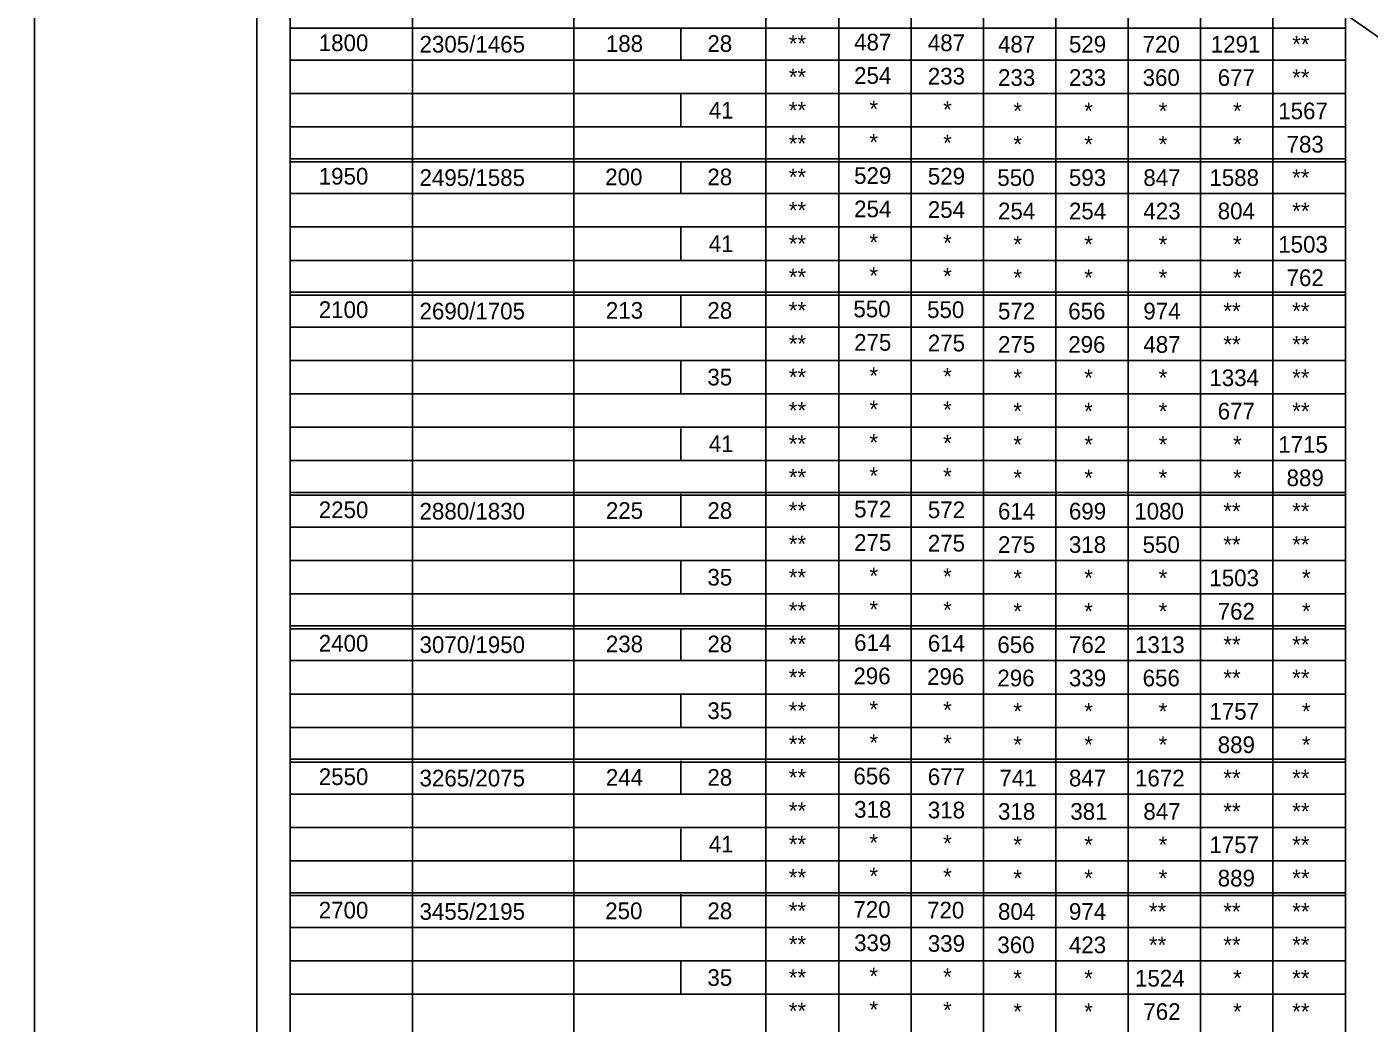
# Model space of a CAD drawing. Extents: x -22562 to -18409, y 3991 to 7171.
# Drawn here: x -21227.2 to -20985.9, y 4239.8 to 4419 of the extents above; entities that cross this region are included whole.
import ezdxf

# ---------------------------------------------------------------- set-up
doc = ezdxf.new("R2010")
doc.units = 0
for name, color, linetype in [('2', 7, 'Continuous'), ('Default', 7, 'Continuous'), ('PLT-BNDY', 7, 'Continuous')]:
    doc.layers.add(name, color=color, linetype=linetype)

msp = doc.modelspace()

# ---------------------------------------------------------------- linework, layer by layer
at = {"layer": '2'}
for p, q in [((-21185.85, 4006.37), (-21185.85, 4570.37)), ((-21179.85, 4553.87), (-21179.85, 4190.99)), ((-20990.1, 4553.87), (-20990.1, 4190.99)), ((-21094.35, 4546.12), (-21094.35, 4190.99)), ((-21157.85, 4540.37), (-21157.85, 4190.99)), ((-21128.85, 4540.37), (-21128.85, 4190.99)), ((-21081.22, 4540.37), (-21081.22, 4190.99)), ((-21068.22, 4540.37), (-21068.22, 4190.99)), ((-21055.22, 4540.37), (-21055.22, 4190.99)), ((-21042.22, 4540.37), (-21042.22, 4190.99)), ((-21029.22, 4540.37), (-21029.22, 4190.99)), ((-21016.22, 4540.37), (-21016.22, 4190.99)), ((-21003.22, 4540.37), (-21003.22, 4190.99)), ((-21179.85, 4418.74), (-20990.1, 4418.74)), ((-21109.6, 4418.74), (-21109.6, 4412.99)), ((-21179.85, 4412.99), (-20990.1, 4412.99)), ((-21179.85, 4406.99), (-20990.1, 4406.99)), ((-21109.6, 4406.99), (-21109.6, 4400.99)), ((-21179.85, 4400.99), (-20990.1, 4400.99)), ((-21179.85, 4395.24), (-20990.1, 4395.24)), ((-21179.85, 4394.74), (-20990.1, 4394.74)), ((-21109.6, 4394.74), (-21109.6, 4388.99)), ((-21179.85, 4388.99), (-20990.1, 4388.99)), ((-21179.85, 4382.99), (-20990.1, 4382.99)), ((-21109.6, 4382.99), (-21109.6, 4376.99)), ((-21179.85, 4376.99), (-20990.1, 4376.99)), ((-21179.85, 4371.24), (-20990.1, 4371.24)), ((-21179.85, 4370.74), (-20990.1, 4370.74)), ((-21109.6, 4370.74), (-21109.6, 4364.99)), ((-21179.85, 4364.99), (-20990.1, 4364.99)), ((-21179.85, 4358.99), (-20990.1, 4358.99)), ((-21109.6, 4358.99), (-21109.6, 4352.99)), ((-21179.85, 4352.99), (-20990.1, 4352.99)), ((-21179.85, 4346.99), (-20990.1, 4346.99)), ((-21109.6, 4346.74), (-21109.6, 4340.99)), ((-21179.85, 4340.99), (-20990.1, 4340.99)), ((-21179.85, 4335.24), (-20990.1, 4335.24)), ((-21179.85, 4334.74), (-20990.1, 4334.74)), ((-21109.6, 4334.99), (-21109.6, 4328.99)), ((-21179.85, 4328.99), (-20990.1, 4328.99)), ((-21179.85, 4322.99), (-20990.1, 4322.99)), ((-21109.6, 4322.99), (-21109.6, 4316.99)), ((-21179.85, 4316.99), (-20990.1, 4316.99)), ((-21179.85, 4311.24), (-20990.1, 4311.24)), ((-21179.85, 4310.74), (-20990.1, 4310.74)), ((-21109.6, 4310.74), (-21109.6, 4304.99)), ((-21179.85, 4304.99), (-20990.1, 4304.99)), ((-21179.85, 4298.99), (-20990.1, 4298.99)), ((-21109.6, 4298.99), (-21109.6, 4292.99)), ((-21179.85, 4292.99), (-20990.1, 4292.99)), ((-21179.85, 4287.24), (-20990.1, 4287.24)), ((-21179.85, 4286.74), (-20990.1, 4286.74)), ((-21109.6, 4286.99), (-21109.6, 4280.99)), ((-21179.85, 4280.99), (-20990.1, 4280.99)), ((-21179.85, 4274.99), (-20990.1, 4274.99)), ((-21109.6, 4274.74), (-21109.6, 4268.99)), ((-21179.85, 4268.99), (-20990.1, 4268.99)), ((-21179.85, 4263.24), (-20990.1, 4263.24)), ((-21179.85, 4262.74), (-20990.1, 4262.74)), ((-21109.6, 4262.99), (-21109.6, 4256.99)), ((-21179.85, 4256.99), (-20990.1, 4256.99)), ((-21179.85, 4250.99), (-20990.1, 4250.99)), ((-21109.6, 4250.99), (-21109.6, 4244.99)), ((-21179.85, 4244.99), (-20990.1, 4244.99))]:
    msp.add_line(p, q, dxfattribs=at)
at = {"layer": 'Default'}
msp.add_line((-21217.79, 4580.96), (-20390.57, 4000.73), dxfattribs=at)
at = {"layer": 'PLT-BNDY'}
for points in [[(-22066.85, 4585.37), (-21225.85, 4585.37), (-21225.85, 3991.37), (-22066.85, 3991.37)], [(-21225.85, 4585.37), (-20384.85, 4585.37), (-20384.85, 3991.37), (-21225.85, 3991.37)]]:
    msp.add_lwpolyline(points, close=True, dxfattribs=at)

# ---------------------------------------------------------------- texts
at = {"layer": '2'}
for s, p in [('1800', (-21174.72, 4414.62)), ('2305/1465', (-21156.6, 4414.37)), ('188', (-21123.1, 4414.49)), ('28', (-21104.85, 4414.49)), ('**', (-21090.22, 4414.49)), ('487', (-21078.47, 4414.74)), ('487', (-21065.22, 4414.62)), ('487', (-21052.6, 4414.37)), ('529', (-21039.85, 4414.37)), ('720', (-21026.6, 4414.37)), ('1291', (-21014.35, 4414.37)), ('**', (-20999.72, 4414.37)), ('**', (-21090.22, 4408.49)), ('254', (-21078.47, 4408.74)), ('233', (-21065.22, 4408.62)), ('233', (-21052.6, 4408.37)), ('233', (-21039.85, 4408.37)), ('360', (-21026.6, 4408.37)), ('677', (-21013.1, 4408.37)), ('**', (-20999.72, 4408.37)), ('41', (-21104.6, 4402.49)), ('**', (-21090.22, 4402.49)), ('*', (-21075.72, 4402.74)), ('*', (-21062.47, 4402.62)), ('*', (-21049.85, 4402.37)), ('*', (-21037.1, 4402.37)), ('*', (-21023.72, 4402.37)), ('*', (-21010.35, 4402.37)), ('1567', (-21002.22, 4402.37)), ('**', (-21090.22, 4396.49)), ('*', (-21075.72, 4396.74)), ('*', (-21062.47, 4396.62)), ('*', (-21049.85, 4396.37)), ('*', (-21037.1, 4396.37)), ('*', (-21023.72, 4396.37)), ('*', (-21010.35, 4396.37)), ('783', (-21000.72, 4396.37)), ('1950', (-21174.72, 4390.62)), ('2495/1585', (-21156.6, 4390.37)), ('200', (-21123.22, 4390.49)), ('28', (-21104.85, 4390.49)), ('**', (-21090.22, 4390.49)), ('529', (-21078.47, 4390.74)), ('529', (-21065.22, 4390.62)), ('550', (-21052.72, 4390.37)), ('593', (-21039.85, 4390.37)), ('847', (-21026.47, 4390.37)), ('1588', (-21014.6, 4390.37)), ('**', (-20999.72, 4390.37)), ('**', (-21090.22, 4384.49)), ('254', (-21078.47, 4384.74)), ('254', (-21065.22, 4384.62)), ('254', (-21052.6, 4384.37)), ('254', (-21039.85, 4384.37)), ('423', (-21026.47, 4384.37)), ('804', (-21013.1, 4384.37)), ('**', (-20999.72, 4384.37)), ('41', (-21104.6, 4378.49)), ('**', (-21090.22, 4378.49)), ('*', (-21075.72, 4378.74)), ('*', (-21062.47, 4378.62)), ('*', (-21049.85, 4378.37)), ('*', (-21037.1, 4378.37)), ('*', (-21023.72, 4378.37)), ('*', (-21010.35, 4378.37)), ('1503', (-21002.22, 4378.37)), ('**', (-21090.22, 4372.49)), ('*', (-21075.72, 4372.74)), ('*', (-21062.47, 4372.62)), ('*', (-21049.85, 4372.37)), ('*', (-21037.1, 4372.37)), ('*', (-21023.72, 4372.37)), ('*', (-21010.35, 4372.37)), ('762', (-21000.72, 4372.37)), ('2100', (-21174.72, 4366.62)), ('2690/1705', (-21156.6, 4366.37)), ('213', (-21123.1, 4366.49)), ('28', (-21104.85, 4366.49)), ('**', (-21090.22, 4366.49)), ('550', (-21078.6, 4366.74)), ('550', (-21065.35, 4366.62)), ('572', (-21052.6, 4366.37)), ('656', (-21039.97, 4366.37)), ('974', (-21026.47, 4366.37)), ('**', (-21012.1, 4366.37)), ('**', (-20999.72, 4366.37)), ('**', (-21090.22, 4360.49)), ('275', (-21078.47, 4360.74)), ('275', (-21065.22, 4360.62)), ('275', (-21052.6, 4360.37)), ('296', (-21039.97, 4360.37)), ('487', (-21026.47, 4360.37)), ('**', (-21012.1, 4360.37)), ('**', (-20999.72, 4360.37)), ('35', (-21104.85, 4354.49)), ('**', (-21090.22, 4354.49)), ('*', (-21075.72, 4354.74)), ('*', (-21062.47, 4354.62)), ('*', (-21049.85, 4354.37)), ('*', (-21037.1, 4354.37)), ('*', (-21023.72, 4354.37)), ('1334', (-21014.6, 4354.37)), ('**', (-20999.72, 4354.37)), ('**', (-21090.22, 4348.49)), ('*', (-21075.72, 4348.74)), ('*', (-21062.47, 4348.62)), ('*', (-21049.85, 4348.37)), ('*', (-21037.1, 4348.37)), ('*', (-21023.72, 4348.37)), ('677', (-21013.1, 4348.37)), ('**', (-20999.72, 4348.37)), ('41', (-21104.6, 4342.49)), ('**', (-21090.22, 4342.49)), ('*', (-21075.72, 4342.74)), ('*', (-21062.47, 4342.62)), ('*', (-21049.85, 4342.37)), ('*', (-21037.1, 4342.37)), ('*', (-21023.72, 4342.37)), ('*', (-21010.35, 4342.37)), ('1715', (-21002.22, 4342.37)), ('**', (-21090.22, 4336.49)), ('*', (-21075.72, 4336.74)), ('*', (-21062.47, 4336.62)), ('*', (-21049.85, 4336.37)), ('*', (-21037.1, 4336.37)), ('*', (-21023.72, 4336.37)), ('*', (-21010.35, 4336.37)), ('889', (-21000.72, 4336.37)), ('2250', (-21174.72, 4330.62)), ('2880/1830', (-21156.6, 4330.37)), ('225', (-21123.1, 4330.49)), ('28', (-21104.85, 4330.49)), ('**', (-21090.22, 4330.49)), ('572', (-21078.47, 4330.74)), ('572', (-21065.22, 4330.62)), ('614', (-21052.6, 4330.37)), ('699', (-21039.85, 4330.37)), ('1080', (-21028.1, 4330.37)), ('**', (-21012.1, 4330.37)), ('**', (-20999.72, 4330.37)), ('**', (-21090.22, 4324.49)), ('275', (-21078.47, 4324.74)), ('275', (-21065.22, 4324.62)), ('275', (-21052.6, 4324.37)), ('318', (-21039.85, 4324.37)), ('550', (-21026.6, 4324.37)), ('**', (-21012.1, 4324.37)), ('**', (-20999.72, 4324.37)), ('35', (-21104.85, 4318.49)), ('**', (-21090.22, 4318.49)), ('*', (-21075.72, 4318.74)), ('*', (-21062.47, 4318.62)), ('*', (-21049.85, 4318.37)), ('*', (-21037.1, 4318.37)), ('*', (-21023.72, 4318.37)), ('1503', (-21014.6, 4318.37)), ('*', (-20997.97, 4318.37)), ('**', (-21090.22, 4312.49)), ('*', (-21075.72, 4312.74)), ('*', (-21062.47, 4312.62)), ('*', (-21049.85, 4312.37)), ('*', (-21037.1, 4312.37)), ('*', (-21023.72, 4312.37)), ('762', (-21013.1, 4312.37)), ('*', (-20997.97, 4312.37)), ('2400', (-21174.72, 4306.62)), ('3070/1950', (-21156.6, 4306.37)), ('238', (-21123.1, 4306.49)), ('28', (-21104.85, 4306.49)), ('**', (-21090.22, 4306.49)), ('614', (-21078.47, 4306.74)), ('614', (-21065.22, 4306.62)), ('656', (-21052.72, 4306.37)), ('762', (-21039.85, 4306.37)), ('1313', (-21027.97, 4306.37)), ('**', (-21012.1, 4306.37)), ('**', (-20999.72, 4306.37)), ('**', (-21090.22, 4300.49)), ('296', (-21078.6, 4300.74)), ('296', (-21065.35, 4300.62)), ('296', (-21052.72, 4300.37)), ('339', (-21039.85, 4300.37)), ('656', (-21026.6, 4300.37)), ('**', (-21012.1, 4300.37)), ('**', (-20999.72, 4300.37)), ('35', (-21104.85, 4294.49)), ('**', (-21090.22, 4294.49)), ('*', (-21075.72, 4294.74)), ('*', (-21062.47, 4294.62)), ('*', (-21049.85, 4294.37)), ('*', (-21037.1, 4294.37)), ('*', (-21023.72, 4294.37)), ('1757', (-21014.6, 4294.37)), ('*', (-20997.97, 4294.37)), ('**', (-21090.22, 4288.49)), ('*', (-21075.72, 4288.74)), ('*', (-21062.47, 4288.62)), ('*', (-21049.85, 4288.37)), ('*', (-21037.1, 4288.37)), ('*', (-21023.72, 4288.37)), ('889', (-21013.1, 4288.37)), ('*', (-20997.97, 4288.37)), ('2550', (-21174.72, 4282.62)), ('3265/2075', (-21156.6, 4282.37)), ('244', (-21123.1, 4282.49)), ('28', (-21104.85, 4282.49)), ('**', (-21090.22, 4282.49)), ('656', (-21078.6, 4282.74)), ('677', (-21065.22, 4282.62)), ('741', (-21052.35, 4282.37)), ('847', (-21039.85, 4282.37)), ('1672', (-21027.97, 4282.37)), ('**', (-21012.1, 4282.37)), ('**', (-20999.72, 4282.37)), ('**', (-21090.22, 4276.49)), ('318', (-21078.47, 4276.74)), ('318', (-21065.22, 4276.62)), ('318', (-21052.6, 4276.37)), ('381', (-21039.6, 4276.37)), ('847', (-21026.47, 4276.37)), ('**', (-21012.1, 4276.37)), ('**', (-20999.72, 4276.37)), ('41', (-21104.6, 4270.49)), ('**', (-21090.22, 4270.49)), ('*', (-21075.72, 4270.74)), ('*', (-21062.47, 4270.62)), ('*', (-21049.85, 4270.37)), ('*', (-21037.1, 4270.37)), ('*', (-21023.72, 4270.37)), ('1757', (-21014.6, 4270.37)), ('**', (-20999.72, 4270.37)), ('**', (-21090.22, 4264.49)), ('*', (-21075.72, 4264.74)), ('*', (-21062.47, 4264.62)), ('*', (-21049.85, 4264.37)), ('*', (-21037.1, 4264.37)), ('*', (-21023.72, 4264.37)), ('889', (-21013.1, 4264.37)), ('**', (-20999.72, 4264.37)), ('720', (-21078.6, 4258.74)), ('2700', (-21174.72, 4258.62)), ('3455/2195', (-21156.6, 4258.37)), ('250', (-21123.22, 4258.49)), ('28', (-21104.85, 4258.49)), ('**', (-21090.22, 4258.49)), ('720', (-21065.35, 4258.62)), ('804', (-21052.6, 4258.37)), ('974', (-21039.85, 4258.37)), ('**', (-21025.47, 4258.37)), ('**', (-21012.1, 4258.37)), ('**', (-20999.72, 4258.37)), ('**', (-21090.22, 4252.49)), ('339', (-21078.47, 4252.74)), ('339', (-21065.22, 4252.62)), ('360', (-21052.72, 4252.37)), ('423', (-21039.85, 4252.37)), ('**', (-21025.47, 4252.37)), ('**', (-21012.1, 4252.37)), ('**', (-20999.72, 4252.37)), ('*', (-21075.72, 4246.74)), ('35', (-21104.85, 4246.49)), ('**', (-21090.22, 4246.49)), ('*', (-21062.47, 4246.62)), ('*', (-21049.85, 4246.37)), ('*', (-21037.1, 4246.37)), ('1524', (-21027.97, 4246.37)), ('*', (-21010.35, 4246.37)), ('**', (-20999.72, 4246.37)), ('**', (-21090.22, 4240.49)), ('*', (-21075.72, 4240.74)), ('*', (-21062.47, 4240.62)), ('*', (-21049.85, 4240.37)), ('*', (-21037.1, 4240.37)), ('762', (-21026.47, 4240.37)), ('*', (-21010.35, 4240.37)), ('**', (-20999.72, 4240.37))]:
    msp.add_text(s, height=3, dxfattribs=at).set_placement(p)

doc.saveas('drawing.dxf')
